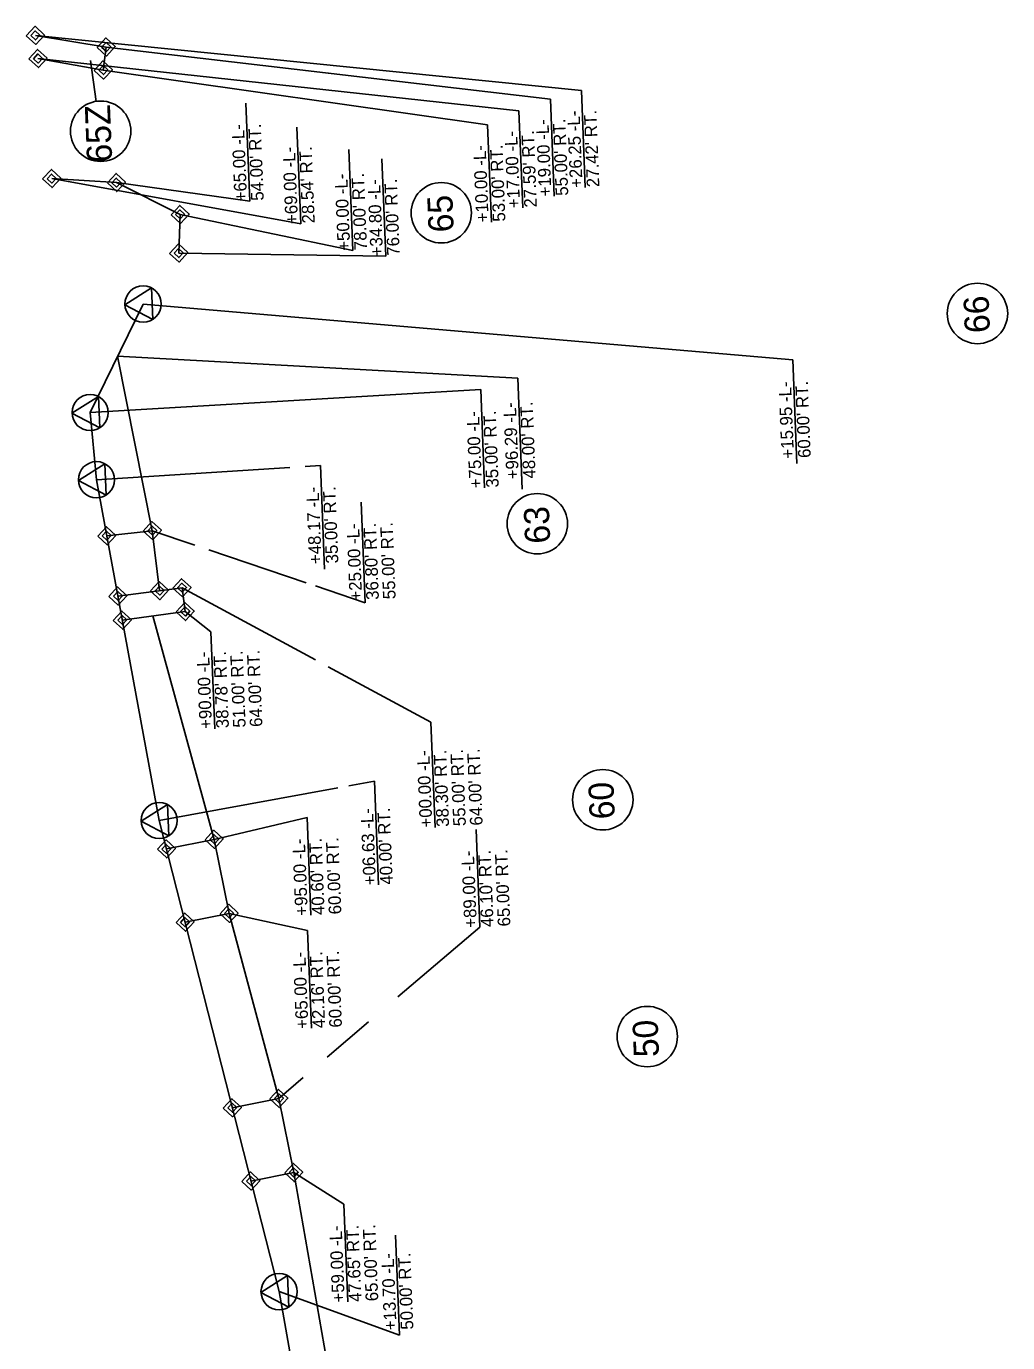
# Model space of a CAD drawing. Extents: x 1627970 to 1628801, y 761752 to 765698.
# Drawn here: x 1628296 to 1628686, y 765175 to 765698 of the extents above; entities that cross this region are included whole.
import ezdxf

# ---------------------------------------------------------------- set-up
doc = ezdxf.new("R2010")
doc.units = 0
for name, color, linetype in [('Exist Property Line Leader', 7, 'Continuous'), ('Exist Property Line Text', 7, 'Continuous'), ('Exist Right of Way Control of Access Line', 7, 'Continuous'), ('Exist Right of Way Easement Line', 7, 'Continuous'), ('Exist Right of Way Monument Leader', 7, 'Continuous'), ('Exist Right of Way Monument Text', 7, 'Continuous'), ('Exist Roads EOT', 7, 'Continuous'), ('Exist Structure Major Deck Tunnel Box Culvert', 7, 'Continuous'), ('Exist Utilities Gas UG Line', 7, 'Continuous'), ('Exist Utilities Gas UG Line Text', 7, 'Continuous'), ('Exist Utilities Other Unknown UG SUE Text', 7, 'Continuous')]:
    doc.layers.add(name, color=color, linetype=linetype)

msp = doc.modelspace()

# ---------------------------------------------------------------- linework, layer by layer
at = {"layer": 'Exist Property Line Leader'}
for p, q in [((1628327.89, 765689.58), (1628299.75, 765694.2)), ((1628326.74, 765680.43), (1628327.89, 765689.58)), ((1628300.79, 765685.01), (1628326.74, 765680.43)), ((1628331.97, 765635.72), (1628306.24, 765637.31)), ((1628357.27, 765623.04), (1628331.97, 765635.72)), ((1628356.71, 765607.72), (1628357.27, 765623.04)), ((1628358.02, 765474.72), (1628332.53, 765471.4)), ((1628359.28, 765465.27), (1628358.02, 765474.72)), ((1628334.3, 765461.83), (1628359.28, 765465.27))]:
    msp.add_line(p, q, dxfattribs=at)
at = {"layer": 'Exist Property Line Text'}
for p, q in [((1628325.7, 765656.12), (1628325.7, 765656.12)), ((1628461.04, 765623.7), (1628461.04, 765623.7)), ((1628674.13, 765583.69), (1628674.13, 765583.69)), ((1628499.21, 765500.14), (1628499.21, 765500.14)), ((1628525.24, 765390.45), (1628525.24, 765390.45)), ((1628542.91, 765296.36), (1628542.91, 765296.36))]:
    msp.add_line(p, q, dxfattribs=at)
for centre in [(1628325.7, 765656.12), (1628461.04, 765623.7), (1628674.13, 765583.69), (1628499.21, 765500.14), (1628525.24, 765390.45), (1628542.91, 765296.36)]:
    msp.add_circle(centre, 12, dxfattribs=at)
at = {"layer": 'Exist Right of Way Control of Access Line'}
for p, q in [((1628321.51, 765544.33), (1628342.55, 765587.45)), ((1628324.03, 765517.62), (1628321.51, 765544.33)), ((1628348.95, 765382.2), (1628324.03, 765517.62)), ((1628396.6, 765194.98), (1628348.95, 765382.2)), ((1628423.08, 765048.13), (1628396.6, 765194.98))]:
    msp.add_line(p, q, dxfattribs=at)
at = {"layer": 'Exist Right of Way Easement Line'}
for p, q in [((1628429.25, 765508.69), (1628430.83, 765468.76)), ((1628346.22, 765497.38), (1628363.17, 765491.65)), ((1628368.64, 765489.79), (1628407.37, 765476.7)), ((1628411.06, 765475.45), (1628430.83, 765468.76)), ((1628370.85, 765374.72), (1628407.69, 765383.46)), ((1628407.69, 765383.46), (1628409.22, 765344.64)), ((1628474.85, 765378.66), (1628476.38, 765339.84)), ((1628376.73, 765345.3), (1628407.91, 765338.46)), ((1628407.91, 765338.46), (1628409.44, 765299.64)), ((1628443.84, 765312.09), (1628476.38, 765339.84)), ((1628415.71, 765288.11), (1628432.19, 765302.16)), ((1628396.54, 765271.76), (1628406.23, 765280.02)), ((1628402.42, 765242.34), (1628422.34, 765229.72)), ((1628422.34, 765229.72), (1628423.87, 765190.9))]:
    msp.add_line(p, q, dxfattribs=at)
at = {"layer": 'Exist Right of Way Monument Leader'}
for points in [[(1628296.15, 765694.06), (1628299.61, 765697.8), (1628303.35, 765694.34), (1628299.89, 765690.61)], [(1628297.95, 765694.13), (1628299.68, 765696), (1628301.55, 765694.27), (1628299.82, 765692.4)], [(1628324.29, 765689.43), (1628327.75, 765693.17), (1628331.48, 765689.72), (1628328.03, 765685.98)], [(1628297.19, 765684.87), (1628300.65, 765688.61), (1628304.39, 765685.15), (1628300.93, 765681.41)], [(1628298.99, 765684.94), (1628300.72, 765686.81), (1628302.59, 765685.08), (1628300.86, 765683.21)], [(1628326.09, 765689.51), (1628327.82, 765691.37), (1628329.69, 765689.65), (1628327.96, 765687.78)], [(1628323.15, 765680.29), (1628326.6, 765684.03), (1628330.34, 765680.57), (1628326.88, 765676.83)], [(1628324.94, 765680.36), (1628326.67, 765682.23), (1628328.54, 765680.5), (1628326.81, 765678.63)], [(1628302.64, 765637.17), (1628306.1, 765640.91), (1628309.84, 765637.45), (1628306.38, 765633.71)], [(1628328.37, 765635.58), (1628331.82, 765639.32), (1628335.56, 765635.86), (1628332.11, 765632.12)], [(1628304.44, 765637.24), (1628306.17, 765639.11), (1628308.04, 765637.38), (1628306.31, 765635.51)], [(1628330.17, 765635.65), (1628331.9, 765637.52), (1628333.76, 765635.79), (1628332.04, 765633.92)], [(1628353.67, 765622.9), (1628357.13, 765626.64), (1628360.87, 765623.18), (1628357.41, 765619.45)], [(1628355.47, 765622.97), (1628357.2, 765624.84), (1628359.07, 765623.11), (1628357.34, 765621.24)], [(1628353.11, 765607.58), (1628356.56, 765611.32), (1628360.3, 765607.86), (1628356.85, 765604.12)], [(1628354.91, 765607.65), (1628356.64, 765609.52), (1628358.5, 765607.79), (1628356.78, 765605.92)], [(1628324.53, 765495.22), (1628327.98, 765498.96), (1628331.72, 765495.5), (1628328.27, 765491.77)], [(1628342.62, 765497.24), (1628346.07, 765500.98), (1628349.81, 765497.52), (1628346.36, 765493.78)], [(1628344.42, 765497.31), (1628346.14, 765499.18), (1628348.01, 765497.45), (1628346.29, 765495.58)], [(1628326.33, 765495.29), (1628328.05, 765497.16), (1628329.92, 765495.43), (1628328.2, 765493.56)], [(1628345.49, 765473.41), (1628348.95, 765477.15), (1628352.69, 765473.7), (1628349.23, 765469.96)], [(1628354.42, 765474.57), (1628357.87, 765478.31), (1628361.61, 765474.86), (1628358.16, 765471.12)], [(1628328.94, 765471.26), (1628332.39, 765475), (1628336.13, 765471.55), (1628332.68, 765467.81)], [(1628330.74, 765471.33), (1628332.46, 765473.2), (1628334.33, 765471.47), (1628332.61, 765469.61)], [(1628347.29, 765473.49), (1628349.02, 765475.35), (1628350.89, 765473.63), (1628349.16, 765471.76)], [(1628356.22, 765474.65), (1628357.95, 765476.51), (1628359.81, 765474.79), (1628358.09, 765472.92)], [(1628355.68, 765465.13), (1628359.14, 765468.86), (1628362.88, 765465.41), (1628359.42, 765461.67)], [(1628357.48, 765465.2), (1628359.21, 765467.07), (1628361.08, 765465.34), (1628359.35, 765463.47)], [(1628330.7, 765461.69), (1628334.15, 765465.43), (1628337.89, 765461.98), (1628334.44, 765458.24)], [(1628332.5, 765461.76), (1628334.22, 765463.63), (1628336.09, 765461.91), (1628334.37, 765460.04)], [(1628367.25, 765374.58), (1628370.7, 765378.32), (1628374.44, 765374.86), (1628370.99, 765371.12)], [(1628348.23, 765370.77), (1628351.68, 765374.51), (1628355.42, 765371.06), (1628351.97, 765367.32)], [(1628350.03, 765370.85), (1628351.75, 765372.72), (1628353.62, 765370.99), (1628351.9, 765369.12)], [(1628369.05, 765374.65), (1628370.77, 765376.52), (1628372.64, 765374.79), (1628370.92, 765372.92)], [(1628373.13, 765345.16), (1628376.59, 765348.9), (1628380.33, 765345.45), (1628376.87, 765341.71)], [(1628374.93, 765345.23), (1628376.66, 765347.1), (1628378.53, 765345.37), (1628376.8, 765343.51)], [(1628355.64, 765341.66), (1628359.09, 765345.4), (1628362.83, 765341.95), (1628359.38, 765338.21)], [(1628357.44, 765341.73), (1628359.16, 765343.6), (1628361.03, 765341.88), (1628359.3, 765340.01)], [(1628392.94, 765271.62), (1628396.4, 765275.36), (1628400.13, 765271.9), (1628396.68, 765268.16)], [(1628394.74, 765271.69), (1628396.47, 765273.56), (1628398.34, 765271.83), (1628396.61, 765269.96)], [(1628374.41, 765267.91), (1628377.86, 765271.65), (1628381.6, 765268.19), (1628378.14, 765264.46)], [(1628376.2, 765267.98), (1628377.93, 765269.85), (1628379.8, 765268.12), (1628378.07, 765266.25)], [(1628381.81, 765238.8), (1628385.27, 765242.54), (1628389.01, 765239.08), (1628385.55, 765235.34)], [(1628398.83, 765242.2), (1628402.28, 765245.94), (1628406.02, 765242.49), (1628402.56, 765238.75)], [(1628400.62, 765242.27), (1628402.35, 765244.14), (1628404.22, 765242.41), (1628402.49, 765240.54)], [(1628383.61, 765238.87), (1628385.34, 765240.74), (1628387.21, 765239.01), (1628385.48, 765237.14)]]:
    msp.add_lwpolyline(points, close=True, dxfattribs=at)
at = {"layer": 'Exist Right of Way Monument Text'}
for p, q in [((1628346.22, 765497.38), (1628332.45, 765566.75)), ((1628370.85, 765374.72), (1628346.4, 765463.5)), ((1628396.54, 765271.76), (1628376.73, 765345.3)), ((1628435.63, 765053.51), (1628402.42, 765242.34))]:
    msp.add_line(p, q, dxfattribs=at)
at = {"layer": 'Exist Roads EOT'}
for p, q in [((1628299.75, 765694.2), (1628516.77, 765672.31)), ((1628327.89, 765689.58), (1628504.4, 765668.89)), ((1628300.79, 765685.01), (1628491.93, 765664.24)), ((1628326.74, 765680.43), (1628479.45, 765658.62)), ((1628518.29, 765633.7), (1628516.77, 765672.31)), ((1628384.93, 765628.31), (1628383.39, 765667.28)), ((1628505.92, 765630.28), (1628504.4, 765668.89)), ((1628493.45, 765625.62), (1628491.93, 765664.24)), ((1628405.18, 765619.31), (1628403.6, 765657.78)), ((1628480.97, 765620), (1628479.45, 765658.62)), ((1628425.95, 765608.68), (1628424.37, 765648.83)), ((1628438.98, 765606.47), (1628437.45, 765645.08)), ((1628405.18, 765619.31), (1628306.24, 765637.31)), ((1628384.93, 765628.31), (1628331.97, 765635.72)), ((1628357.27, 765623.04), (1628425.95, 765608.68)), ((1628356.71, 765607.72), (1628438.98, 765606.47)), ((1628358.02, 765474.72), (1628411.06, 765446.06)), ((1628359.28, 765465.27), (1628369.49, 765457.17)), ((1628371.06, 765418.69), (1628369.49, 765457.17)), ((1628416.1, 765443.33), (1628456.87, 765421.3)), ((1628458.58, 765379.49), (1628456.87, 765421.3))]:
    msp.add_line(p, q, dxfattribs=at)
at = {"layer": 'Exist Structure Major Deck Tunnel Box Culvert'}
for p, q in [((1628346.22, 765497.38), (1628328.12, 765495.36)), ((1628349.09, 765473.56), (1628346.22, 765497.38)), ((1628370.85, 765374.72), (1628351.83, 765370.92)), ((1628376.73, 765345.3), (1628370.85, 765374.72)), ((1628359.23, 765341.8), (1628376.73, 765345.3)), ((1628396.54, 765271.76), (1628378, 765268.05)), ((1628402.42, 765242.34), (1628396.54, 765271.76)), ((1628385.41, 765238.94), (1628402.42, 765242.34))]:
    msp.add_line(p, q, dxfattribs=at)
at = {"layer": 'Exist Utilities Gas UG Line'}
for p, q in [((1628323.97, 765667.99), (1628321.6, 765684.22)), ((1628342.55, 765587.45), (1628600.72, 765565.28)), ((1628600.72, 765565.28), (1628602.35, 765524.03)), ((1628476.73, 765553.51), (1628321.51, 765544.33)), ((1628476.73, 765553.51), (1628478.27, 765514.43)), ((1628400.9, 765522.52), (1628324.03, 765517.62)), ((1628413.02, 765523.29), (1628406.98, 765522.9)), ((1628413.02, 765523.29), (1628414.64, 765482.12)), ((1628348.95, 765382.2), (1628419.93, 765395.18)), ((1628424.36, 765395.99), (1628434.49, 765397.84)), ((1628434.49, 765397.84), (1628436.12, 765356.67)), ((1628442.87, 765217.44), (1628444.44, 765177.66)), ((1628396.6, 765194.98), (1628444.44, 765177.66))]:
    msp.add_line(p, q, dxfattribs=at)
at = {"layer": 'Exist Utilities Gas UG Line Text'}
for q in [(1628332.45, 765566.75), (1628493.15, 765513.94)]:
    msp.add_line((1628491.41, 765558.04), q, dxfattribs=at)
at = {"layer": 'Exist Utilities Other Unknown UG SUE Text'}
for p, q in [((1628299.75, 765694.2), (1628299.75, 765694.2)), ((1628327.89, 765689.58), (1628327.89, 765689.58)), ((1628300.79, 765685.01), (1628300.79, 765685.01)), ((1628326.74, 765680.43), (1628326.74, 765680.43)), ((1628306.24, 765637.31), (1628306.24, 765637.31)), ((1628331.97, 765635.72), (1628331.97, 765635.72)), ((1628357.27, 765623.04), (1628357.27, 765623.04)), ((1628356.71, 765607.72), (1628356.71, 765607.72)), ((1628342.55, 765587.45), (1628342.55, 765587.45)), ((1628321.51, 765544.33), (1628321.51, 765544.33)), ((1628324.03, 765517.62), (1628324.03, 765517.62)), ((1628328.12, 765495.36), (1628328.12, 765495.36)), ((1628346.22, 765497.38), (1628346.22, 765497.38)), ((1628349.09, 765473.56), (1628349.09, 765473.56)), ((1628358.02, 765474.72), (1628358.02, 765474.72)), ((1628332.53, 765471.4), (1628332.53, 765471.4)), ((1628334.3, 765461.83), (1628334.3, 765461.83)), ((1628359.28, 765465.27), (1628359.28, 765465.27)), ((1628348.95, 765382.2), (1628348.95, 765382.2)), ((1628370.85, 765374.72), (1628370.85, 765374.72)), ((1628351.83, 765370.92), (1628351.83, 765370.92)), ((1628359.23, 765341.8), (1628359.23, 765341.8)), ((1628376.73, 765345.3), (1628376.73, 765345.3)), ((1628378, 765268.05), (1628378, 765268.05)), ((1628396.54, 765271.76), (1628396.54, 765271.76)), ((1628402.42, 765242.34), (1628402.42, 765242.34)), ((1628385.41, 765238.94), (1628385.41, 765238.94)), ((1628396.6, 765194.98), (1628396.6, 765194.98))]:
    msp.add_line(p, q, dxfattribs=at)
for points in [[(1628335.34, 765587.18), (1628345.91, 765593.82), (1628346.4, 765581.35)], [(1628314.3, 765544.06), (1628324.86, 765550.7), (1628325.36, 765538.23)], [(1628316.82, 765517.35), (1628327.39, 765523.99), (1628327.88, 765511.52)], [(1628341.75, 765381.93), (1628352.31, 765388.57), (1628352.8, 765376.1)], [(1628389.39, 765194.71), (1628399.96, 765201.35), (1628400.45, 765188.88)]]:
    msp.add_lwpolyline(points, close=True, dxfattribs=at)
for centre in [(1628342.55, 765587.45), (1628321.51, 765544.33), (1628324.03, 765517.62), (1628348.95, 765382.2), (1628396.6, 765194.98)]:
    msp.add_circle(centre, 7.2, dxfattribs=at)

# ---------------------------------------------------------------- texts
at = {"layer": 'Exist Property Line Text'}
for s, p in [('65Z', (1628330.29, 765643.85)), ('65', (1628466.02, 765616.11)), ('66', (1628679.11, 765576.1)), ('63', (1628504.37, 765492.42)), ('60', (1628530.04, 765382.87)), ('50', (1628547.59, 765288.34))]:
    msp.add_text(s, height=10, rotation=92.2582, dxfattribs=at).set_placement(p)
at = {"layer": 'Exist Right of Way Easement Line'}
for s, p in [('+25.00 -L-', (1628429.61, 765469.7)), ("36.80' RT.", (1628436.27, 765469.96)), ("55.00' RT.", (1628442.93, 765470.23)), ('+95.00 -L-', (1628408.05, 765344.47)), ("40.60' RT.", (1628414.71, 765344.73)), ("60.00' RT.", (1628421.37, 765345)), ('+89.00 -L-', (1628475.21, 765339.67)), ("46.10' RT.", (1628481.87, 765339.94)), ("65.00' RT.", (1628488.53, 765340.2)), ('+65.00 -L-', (1628408.27, 765299.47)), ("42.16' RT.", (1628414.93, 765299.73)), ("60.00' RT.", (1628421.59, 765300)), ('+59.00 -L-', (1628422.7, 765190.73)), ("47.65' RT.", (1628429.36, 765190.99)), ("65.00' RT.", (1628436.02, 765191.25))]:
    msp.add_text(s, height=5, rotation=92.2582, dxfattribs=at).set_placement(p)
at = {"layer": 'Exist Roads EOT'}
for s, p in [('+19.00 -L-', (1628504.86, 765630.29)), ("55.00' RT.", (1628511.53, 765630.55)), ('+26.25 -L-', (1628517.23, 765633.71)), ("27.42' RT.", (1628523.89, 765633.97)), ('+65.00 -L-', (1628383.87, 765628.32)), ("54.00' RT.", (1628390.53, 765628.59)), ('+17.00 -L-', (1628492.39, 765625.63)), ("27.59' RT.", (1628499.05, 765625.9)), ('+10.00 -L-', (1628479.91, 765620.01)), ("53.00' RT.", (1628486.57, 765620.28)), ('+69.00 -L-', (1628404.12, 765619.32)), ("28.54' RT.", (1628410.78, 765619.59)), ('+50.00 -L-', (1628424.89, 765608.69)), ("78.00' RT.", (1628431.55, 765608.95)), ('+34.80 -L-', (1628437.92, 765606.48)), ("76.00' RT.", (1628444.58, 765606.74)), ('+90.00 -L-', (1628370, 765418.71)), ("38.78' RT.", (1628376.66, 765418.97)), ("51.00' RT.", (1628383.33, 765419.23)), ("64.00' RT.", (1628389.99, 765419.49)), ('+00.00 -L-', (1628457.52, 765379.51)), ("38.30' RT.", (1628464.18, 765379.77)), ("55.00' RT.", (1628470.84, 765380.03)), ("64.00' RT.", (1628477.5, 765380.29))]:
    msp.add_text(s, height=5, rotation=92.2582, dxfattribs=at).set_placement(p)
at = {"layer": 'Exist Utilities Gas UG Line'}
for s, p in [('+15.95 -L-', (1628601.24, 765526.09)), ("60.00' RT.", (1628607.9, 765526.36)), ('+75.00 -L-', (1628477.25, 765514.32)), ("35.00' RT.", (1628483.91, 765514.59)), ('+48.17 -L-', (1628413.53, 765484.18)), ("35.00' RT.", (1628420.19, 765484.44)), ('+06.63 -L-', (1628435.14, 765356.56)), ("40.00' RT.", (1628441.8, 765356.82)), ('+13.70 -L-', (1628443.33, 765179.73)), ("50.00' RT.", (1628449.99, 765179.99))]:
    msp.add_text(s, height=5, rotation=92.2582, dxfattribs=at).set_placement(p)
at = {"layer": 'Exist Utilities Gas UG Line Text'}
for s, p in [('+96.29 -L-', (1628491.9, 765517.9)), ("48.00' RT.", (1628498.56, 765518.17))]:
    msp.add_text(s, height=5, rotation=92.2582, dxfattribs=at).set_placement(p)

doc.saveas('drawing.dxf')
